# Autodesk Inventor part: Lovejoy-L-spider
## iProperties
Author: Ole Germer
Shininess: 20.0
PropertySet Name: _Private Model Information
Created: 2001-03
Part Number: Lovejoy-L-spider
Document SubType Name: Modeling
Designer: Ole Germer
Material: UHMW, Black
Control State: 0
Master: False
Checked Out: False
PropertySet Name: Design Tracking Control
Density: 1.0
Volumn: 297.8891427824034
Area: 475.81343942843256
PropertySet Name: Model Information
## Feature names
1. Extrusion1
2. Hole1
3. Hole2
